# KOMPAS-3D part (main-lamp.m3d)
File: created 02.10.2016 09:40:27, last saved 02.10.2016 09:58:07.
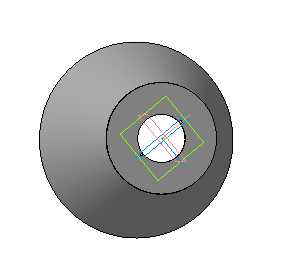
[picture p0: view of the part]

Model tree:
1. Эскиз:1
2. Операция вращения:1
     Угол 1 = 360
3. Эскиз:2
4. Вырезать элемент выдавливания:1
     Расстояние 1 = 60
5. Эскиз:3
6. Операция выдавливания:1
     Расстояние 1 = 10; Расстояние 2 = 40
7. Эскиз:4
8. Вырезать элемент вращения:1
     Угол 1 = 360
9. Эскиз:5
10. Вырезать элемент выдавливания:2
     Расстояние 2 = 150; Расстояние 1 = 150
11. Эскиз:6
12. Вырезать элемент выдавливания:3
     Расстояние 2 = 150; Расстояние 1 = 6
